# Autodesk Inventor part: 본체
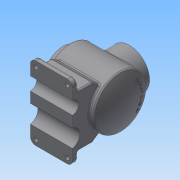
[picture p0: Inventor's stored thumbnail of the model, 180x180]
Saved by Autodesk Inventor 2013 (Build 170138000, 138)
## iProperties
Created: 2018-08
Part Number: 본체
Material: 일반
Document SubType Name: Modeling
Designer: Administrator
Density: 1 g/cm^3
Author: Administrator
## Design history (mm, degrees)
sketch "스케치1"
  geometry: L1 (0, 0)-(0, 38); L2 (0, 38)-(12, 38); L3 (12, 38)-(12, 50); L4 (12, 50)-(108.671, 50); L5 (0, 0)-(120, 0); A1 r 116 centre (4, 0) between (120, 0) and (108.671, 50)
  constraints: 10 end point, 3 parallel, 2 point on circle, 1 centre point, 1 perpendicular, 1 point on line, 1 vertical
  dimensions: "d0" = 12 distance between parallel lines of L3 L1; "d3" = 100 diameter of L4 L5; "d4" = 76 diameter of L2 L5; "d6" = 116 radius of A1; "d7" = 108 distance from line of L5.end L3
revolve "회전1" sketch "스케치1" stored, may be unused: angle "d8" = 90 deg
feature "쉘1" dims "d79" = 10
sketch "스케치2"
  geometry: C1 r 27 at (0, 0); 1 further point
  constraints: 1 centre point, 1 coincident
  dimensions: "d9" = 54 diameter of C1
extrude "돌출1" cut sketch "스케치2" distance "d10" = 50; taper "d11" = 0 deg
node "작업 평면1"
sketch "스케치3"
  geometry: L1 (0, 38)-(0, -38) reference; C1 r 38 at (-62, 0); 2 further points
  constraints: 1 centre point, 1 horizontal alignment, 1 midpoint
  dimensions: "d13" = 76 diameter of C1; "d14" = 62 distance from line of L1 C1.centre
extrude "돌출2" join sketch "스케치3" stored distance "d15" = 50; taper "d16" = 0 deg
sketch "스케치4"
  geometry: C1 r 38 at (0, 0) reference; C2 r 27 at (0, 0); 1 further point
  constraints: 1 centre point, 1 coincident
  dimensions: "d17" = 54 diameter of C2
extrude "돌출3" cut sketch "스케치4" distance "d18" = 50; taper "d19" = 0 deg
sketch "스케치5"
  geometry: 2 further points
  constraints: 1 vertical alignment
  dimensions: "d20" = 32.5 distance of point (0, 0) point (0, 32.5)
hole "구멍1" sketch "스케치5" at (0, 32.5) diameter "d21" = 3.242; stored, may be unused: countersink angle "d25" = 90 deg, drill point angle "d27" = 118 deg; dims "d22" = 8, "d23" = 4, "d24" = 2, "d26" = 10
sketch "스케치6"
  geometry: C1 r 27 at (0, 0) reference; 2 further points
  constraints: 1 vertical alignment
  dimensions: "d31" = 32.5 distance of C1.centre point (0, 32.5)
hole "구멍2" sketch "스케치6" at (0, 32.5) diameter "d32" = 3.242; stored, may be unused: countersink angle "d36" = 90 deg, drill point angle "d38" = 118 deg; dims "d33" = 8, "d34" = 4, "d35" = 2, "d37" = 10
node "작업 평면3"
sketch "스케치7"
  geometry: L1 (20, 70)-(100, 70); L2 (100, 70)-(100, -70); L3 (100, -70)-(20, -70); L4 (20, -70)-(20, 70); L5 (12, -50)-(12, 50) reference; 3 further points
  constraints: 8 end point, 2 midpoint, 2 parallel, 1 horizontal, 1 horizontal alignment, 1 perpendicular
  dimensions: "d44" = 80 distance of L2.end L3.end; "d46" = 140 distance of L1.end L2.end; "d47" = 8 distance between parallel lines of L4 L5
extrude "돌출4" join sketch "스케치7" distance "d48" = 10; taper "d49" = 0 deg
node "작업 평면4"
sketch "스케치8"
  geometry: L1 (65, -37.947)-(32.558, -37.947) reference; L2 (32.558, 37.947)-(65, 37.947) reference; L3 (65, 37.947)-(65, 26.926) reference; L4 (65, 26.926)-(29.58, 26.926) reference; L5 (29.58, -26.926)-(65, -26.926) reference; L6 (65, -26.926)-(65, -37.947) reference; L7 (-82, 70)-(-72, 70) reference; L8 (-72, 70)-(-72, -70) reference; L9 (-72, -70)-(-82, -70) reference; L10 (-82, -70)-(-82, 70) reference; L11 (-29.59, -40.304)-(-72, -70); L12 (-29.59, 40.304)-(-72, 70); A1 r 50 centre (0, 0) between (32.558, 37.947) and (32.558, -37.947) reference; A2 r 40 centre (0, 0) between (29.58, 26.926) and (29.58, -26.926) reference; 1 further point
  constraints: 4 end point, 2 point on circle
  dimensions: "d51" = 35 deg angle of L9 L11; "d52" = 35 deg angle of L7 L12
extrude "돌출5" join sketch "스케치8" stored distance "d53" = 80; taper "d54" = 0 deg
sketch "스케치9"
  geometry: L1 (29.696, 52.41)-(0, 10) reference; L2 (0, 0)-(0, 10) reference; L3 (140, 10)-(110.304, 52.41) reference; L4 (140, 0)-(140, 10) reference; L5 (140, 10)-(120, 10); L6 (120, 10)-(120, 38.563); L7 (0, 10)-(20, 10); L8 (20, 10)-(20, 38.563); 1 further point
  constraints: 8 end point, 4 perpendicular, 2 point on line
  dimensions: "d55" = 20 distance of L3.start L5.end; "d56" = 20 distance of L1.end L7.end
extrude "돌출6" cut sketch "스케치9" stored distance "d57" = 80; taper "d58" = 0 deg
sketch "스케치10"
  geometry: C1 r 17.5 at (47.5, -3.398); C2 r 12.5 at (97.5, -0.502); 1 further point
  constraints: 2 centre point
  dimensions: "d59" = 17.5 radius of C1; "d60" = 12.5 radius of C2; "d61" = 22.5 horizontal distance of C1.centre point (70, 82); "d62" = 27.5 horizontal distance of point (70, 82) C2.centre
extrude "돌출7" cut sketch "스케치10" stored distance "d63" = 80; taper "d64" = 0 deg
node "작업 평면5"
sketch "스케치11"
  geometry: C1 r 32.5 at (0, 0); 1 further point
  constraints: 1 centre point, 1 coincident, 1 other
  dimensions: "d66" = 32.5 radius of C1
feature "엠보싱1" sketch "스케치11" dims "d0" = 12, "d3" = 100, "d4" = 76, "d6" = 116, "d7" = 108, "d67" = 0.5, "d68" = 0
fillet "모깎기1" dims "d69" = 10
sketch "스케치12"
  geometry: A1 r 10 centre (10, 10) between (10, 20) and (0, 10) reference; A2 r 10 centre (70, 10) between (80, 10) and (70, 20) reference; A3 r 10 centre (70, -110) between (70, -120) and (80, -110) reference; A4 r 10 centre (10, -110) between (0, -110) and (10, -120) reference; 5 further points
  constraints: 4 coincident
hole "구멍3" sketch "스케치12" at (10, 10), (70, 10), (70, -110), (10, -110) diameter "d70" = 8; stored, may be unused: countersink angle "d74" = 90 deg, drill point angle "d76" = 118 deg; dims "d71" = 8, "d72" = 4, "d73" = 2, "d75" = 10
fillet "모깎기2" dims "d77" = 3
fillet "모깎기3" dims "d78" = 3
chamfer "모따기1" distance "d83" = 1; stored, may be unused: second distance "d84" = 2, angle "d85" = 45 deg
fillet "모깎기4" dims "d86" = 3
node "솔리드1"
pattern_circular "원형 패턴2" dims angle "d40" = 360 deg
pattern_circular "원형 패턴3" dims angle "d81" = 360 deg
node "절단 모서리 투영1"
other parameters: "d12" = 65, "d43" = -82, "d65" = 193
